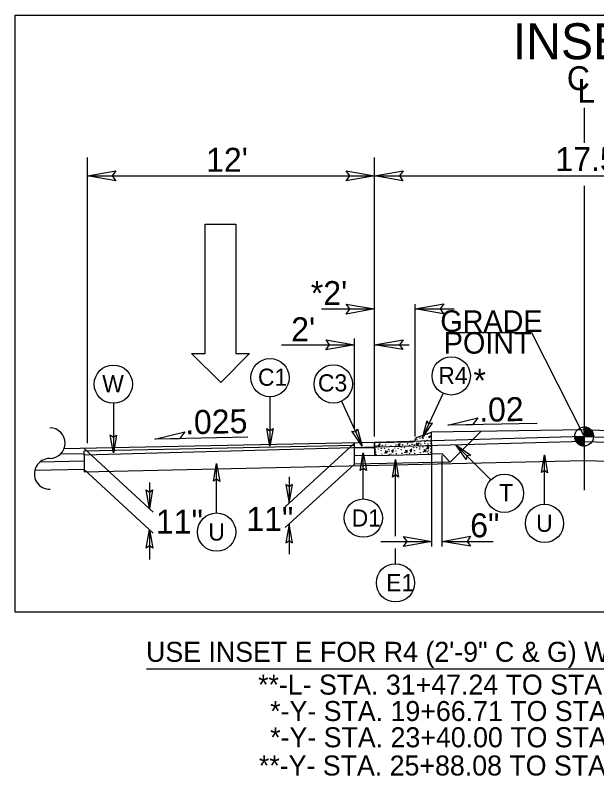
# Model space of a CAD drawing. Extents: x 958711 to 962106, y 831169 to 840840.
# Drawn here: x 959767.6 to 959956.9, y 838795 to 839042.5 of the extents above; entities that cross this region are included whole.
import ezdxf

# ---------------------------------------------------------------- set-up
doc = ezdxf.new("R2010")
doc.units = 0
for name, color, linetype in [('Default', 7, 'Continuous'), ('Old_Level_1', 7, 'Continuous'), ('Old_Level_11', 7, 'Continuous'), ('Old_Level_3', 7, 'Continuous'), ('Prop Dimension Text', 7, 'Continuous'), ('Prop Lane Arrow CELL', 7, 'Continuous'), ('Typical Curb CELL', 7, 'Continuous'), ('Typical ID Circle CELL', 7, 'Continuous'), ('Typical Terminator CELL', 7, 'Continuous'), ('Typical Text Grade Point CELL', 7, 'Continuous'), ('Typical Text ID Circle CELL', 7, 'Continuous')]:
    doc.layers.add(name, color=color, linetype=linetype)

# ---------------------------------------------------------------- blocks, each defined once
blk = doc.blocks.new('Lane Arrow Through')
at = {"layer": 'Prop Lane Arrow CELL'}
for p, q in [((-3.15, 1.6), (-3.15, 3.1)), ((-3.15, 3.1), (0, 0)), ((-17.15, 1.6), (-3.15, 1.6)), ((-17.15, -1.7), (-17.15, 1.6)), ((0, 0), (-3.15, -3.2)), ((-3.15, -1.7), (-17.15, -1.7)), ((-3.15, -3.2), (-3.15, -1.7))]:
    blk.add_line(p, q, dxfattribs=at)

msp = doc.modelspace()

# ---------------------------------------------------------------- linework, layer by layer
at = {"layer": 'Default'}
for p, q in [((959952.78, 839012.37), (959952.78, 839000.98)), ((959952.78, 838987.01), (959952.78, 838887.92)), ((959952.78, 838907.6), (959903.13, 838906.79)), ((959909.22, 838897.09), (959919.17, 838907.05)), ((959952.78, 838907.6), (960002.43, 838906.61))]:
    msp.add_line(p, q, dxfattribs=at)
at = {"layer": 'Old_Level_1'}
for p, q in [((959791.14, 838903.19), (959791.14, 838996.13)), ((959884.62, 838905.42), (959884.62, 838996.13)), ((959791.14, 838990.21), (959884.62, 838990.21)), ((959884.62, 838990.21), (960020.95, 838990.21)), ((959897.84, 838905.42), (959897.84, 838948.48)), ((959867.31, 838946.9), (959884.62, 838946.9)), ((959897.84, 838946.9), (959910.47, 838946.9)), ((959878.02, 838908.11), (959878.02, 838937.33)), ((959854.29, 838935.26), (959878.02, 838935.26)), ((959884.62, 838935.26), (959895.89, 838935.26)), ((959937.48, 838909.64), (959908.42, 838909.05)), ((959952.78, 838905.4), (959952.78, 838908.47)), ((959884.62, 838903.42), (959783.5, 838901.38)), ((959952.78, 838903.76), (959790.06, 838899.33)), ((959843.32, 838905.15), (959813.11, 838904.54)), ((959952.78, 838905.4), (959884.62, 838903.42)), ((959949.72, 838905.4), (959952.78, 838905.4)), ((959955.84, 838905.4), (959952.78, 838905.4)), ((959952.78, 838902.35), (959952.78, 838905.4)), ((959952.78, 838905.4), (959952.78, 838902.35)), ((959952.78, 838905.4), (960020.95, 838903.26)), ((959878.02, 838902.43), (959790.06, 838900.65)), ((959790.06, 838901.51), (959812.57, 838880.8)), ((959878.02, 838903.29), (959855.51, 838882.58)), ((959878.02, 838896.46), (959878.02, 838903.29)), ((959884.66, 838901.7), (959878.02, 838901.56)), ((959790.06, 838899.78), (959782.31, 838899.63)), ((959790.06, 838899.33), (959790.06, 838900.65)), ((959790.06, 838899.33), (959790.06, 838893.87)), ((959884.71, 838899.27), (959878.02, 838899.14)), ((959906.58, 838899.73), (959903.28, 838899.66)), ((959903.28, 838869.65), (959903.28, 838899.66)), ((959906.58, 838899.73), (959909.22, 838897.09)), ((959906.58, 838869.65), (959906.58, 838899.27)), ((959790.06, 838897.36), (959775.63, 838897.06)), ((959878.02, 838896.46), (959855.51, 838875.75)), ((959909.22, 838897.09), (959878.02, 838896.46)), ((959790.06, 838894.68), (959773.99, 838894.36)), ((959790.06, 838894.68), (959812.57, 838873.97)), ((959856.78, 838892.25), (959856.77, 838883.74)), ((959811.3, 838890.47), (959811.31, 838881.96)), ((959856.78, 838876.92), (959856.78, 838867.14)), ((959811.3, 838875.14), (959811.3, 838865.36)), ((959886.68, 838871.29), (959903.28, 838871.29)), ((959906.58, 838871.29), (959923.18, 838871.29)), ((959810.36, 838829.82), (960099.79, 838829.82))]:
    msp.add_line(p, q, dxfattribs=at)
msp.add_lwpolyline([(959767.63, 839042.47), (960126.24, 839042.47), (960126.24, 838848.28), (959767.63, 838848.28)], close=True, dxfattribs=at)
for points in [[(959952.82, 838908.47), (959952.82, 838908.47), (959952.82, 838905.4)], [(959952.87, 838908.47), (959952.87, 838905.4)], [(959952.94, 838908.46), (959952.94, 838905.4)], [(959953, 838908.45), (959953, 838905.4)], [(959953.06, 838908.45), (959953.06, 838905.4)], [(959953.12, 838908.45), (959953.12, 838905.4)], [(959953.19, 838908.44), (959953.19, 838905.4)], [(959953.25, 838908.44), (959953.25, 838905.4)], [(959953.3, 838908.41), (959953.3, 838905.4)], [(959953.36, 838908.41), (959953.36, 838905.4)], [(959953.43, 838908.4), (959953.43, 838905.4)], [(959953.49, 838908.38), (959953.49, 838905.4)], [(959953.55, 838908.36), (959953.55, 838905.4)], [(959953.61, 838908.34), (959953.61, 838905.4)], [(959953.68, 838908.33), (959953.68, 838905.4)], [(959953.73, 838908.31), (959953.73, 838905.4)], [(959953.8, 838908.29), (959953.79, 838905.4)], [(959953.85, 838908.27), (959953.85, 838905.4)], [(959953.91, 838908.25), (959953.91, 838905.4)], [(959953.98, 838908.22), (959953.98, 838905.4)], [(959954.04, 838908.2), (959954.04, 838905.4)], [(959954.1, 838908.16), (959954.1, 838905.4)], [(959954.16, 838908.14), (959954.16, 838905.4)], [(959954.22, 838908.12), (959954.22, 838905.4)], [(959954.28, 838908.08), (959954.28, 838905.4)], [(959954.35, 838908.04), (959954.35, 838905.4)], [(959954.41, 838908), (959954.41, 838905.4)], [(959954.47, 838907.96), (959954.47, 838905.4)], [(959954.53, 838907.91), (959954.53, 838905.4)], [(959954.58, 838907.88), (959954.58, 838905.4)], [(959954.65, 838907.83), (959954.65, 838905.4)], [(959954.71, 838907.78), (959954.71, 838905.4)], [(959954.77, 838907.74), (959954.77, 838905.4)], [(959954.83, 838907.68), (959954.83, 838905.4)], [(959954.89, 838907.62), (959954.89, 838905.4)], [(959954.96, 838907.55), (959954.96, 838905.4)], [(959955.02, 838907.49), (959955.02, 838905.4)], [(959955.08, 838907.43), (959955.08, 838905.4)], [(959955.14, 838907.37), (959955.14, 838905.4)], [(959955.2, 838907.27), (959955.2, 838905.4)], [(959955.27, 838907.2), (959955.27, 838905.4)], [(959955.33, 838907.11), (959955.33, 838905.4)], [(959955.39, 838907.02), (959955.39, 838905.4)], [(959955.44, 838906.92), (959955.44, 838905.4)], [(959955.5, 838906.81), (959955.5, 838905.4)], [(959955.56, 838906.67), (959955.56, 838905.4)], [(959955.63, 838906.52), (959955.63, 838905.4)], [(959955.69, 838906.36), (959955.69, 838905.4)], [(959955.75, 838906.15), (959955.75, 838905.4)], [(959955.81, 838905.85), (959955.81, 838905.4)], [(959949.75, 838905.4), (959949.75, 838905.08)], [(959949.81, 838905.4), (959949.81, 838904.71)], [(959949.87, 838905.4), (959949.87, 838904.49)], [(959949.93, 838905.4), (959949.93, 838904.31)], [(959950, 838905.4), (959950, 838904.17)], [(959950.06, 838905.4), (959950.06, 838904.04)], [(959950.11, 838905.4), (959950.11, 838903.92)], [(959950.17, 838905.4), (959950.17, 838903.81)], [(959950.24, 838905.4), (959950.24, 838903.73)], [(959950.3, 838905.4), (959950.3, 838903.64)], [(959950.36, 838905.4), (959950.36, 838903.54)], [(959950.42, 838905.4), (959950.42, 838903.48)], [(959950.48, 838905.4), (959950.48, 838903.41)], [(959950.54, 838905.4), (959950.54, 838903.33)], [(959950.6, 838905.4), (959950.6, 838903.26)], [(959950.66, 838905.4), (959950.66, 838903.21)], [(959950.73, 838905.4), (959950.73, 838903.16)], [(959950.79, 838905.4), (959950.79, 838903.1)], [(959950.85, 838905.4), (959950.85, 838903.05)], [(959950.91, 838905.4), (959950.91, 838902.99)], [(959950.97, 838905.4), (959950.97, 838902.95)], [(959951.03, 838905.4), (959951.03, 838902.91)], [(959951.09, 838905.4), (959951.09, 838902.87)], [(959951.15, 838905.4), (959951.15, 838902.82)], [(959951.22, 838905.4), (959951.22, 838902.78)], [(959951.28, 838905.4), (959951.28, 838902.74)], [(959951.34, 838905.4), (959951.34, 838902.71)], [(959951.39, 838905.4), (959951.39, 838902.69)], [(959951.45, 838905.4), (959951.45, 838902.66)], [(959951.52, 838905.4), (959951.52, 838902.62)], [(959951.58, 838905.4), (959951.58, 838902.6)], [(959951.64, 838905.4), (959951.64, 838902.57)], [(959951.7, 838905.4), (959951.7, 838902.55)], [(959951.77, 838905.4), (959951.77, 838902.53)], [(959951.82, 838905.4), (959951.82, 838902.5)], [(959951.89, 838905.4), (959951.89, 838902.49)], [(959951.95, 838905.4), (959951.95, 838902.47)], [(959952.01, 838905.4), (959952.01, 838902.45)], [(959952.07, 838905.4), (959952.07, 838902.44)], [(959952.13, 838905.4), (959952.13, 838902.42)], [(959952.2, 838905.4), (959952.2, 838902.41)], [(959952.25, 838905.4), (959952.25, 838902.41)], [(959952.31, 838905.4), (959952.31, 838902.39)], [(959952.37, 838905.4), (959952.37, 838902.37)], [(959952.44, 838905.4), (959952.44, 838902.37)], [(959952.5, 838905.4), (959952.5, 838902.37)], [(959952.56, 838905.4), (959952.56, 838902.35)], [(959952.62, 838905.4), (959952.62, 838902.35)], [(959952.68, 838905.4), (959952.68, 838902.35)], [(959952.74, 838905.4), (959952.74, 838902.35), (959952.74, 838902.35)], [(959952.78, 838903.76), (960111.06, 838899.45)], [(959790.06, 838893.87), (959952.94, 838897.58)], [(959952.94, 838897.58), (960111.06, 838893.27)]]:
    msp.add_lwpolyline(points, dxfattribs=at)
msp.add_circle((959952.79, 838905.41), 3.06, dxfattribs=at)
for centre, radius, start, end in [((959952.79, 838905.41), 3.06, 359.9905, 89.9905), ((959778.86, 838903.25), 5, 270, 90), ((959952.79, 838905.41), 3.06, 179.9905, 269.9905), ((959778.86, 838893.25), 5, 90, 272.2728)]:
    msp.add_arc(centre, radius, start, end, dxfattribs=at)
at = {"layer": 'Old_Level_11'}
for p, q in [((959908.42, 838909.05), (959918.17, 838911.48)), ((959918.17, 838911.48), (959916.44, 838909.21)), ((959916.44, 838909.21), (959908.42, 838909.05)), ((959813.11, 838904.54), (959822.87, 838906.97)), ((959822.87, 838906.97), (959821.13, 838904.7)), ((959821.13, 838904.7), (959813.11, 838904.54))]:
    msp.add_line(p, q, dxfattribs=at)
at = {"layer": 'Typical Curb CELL'}
for p, q in [((959898.29, 838905.05), (959903.13, 838906.78)), ((959903.28, 838899.66), (959903.13, 838906.78)), ((959884.62, 838903.42), (959897.19, 838903.69)), ((959884.62, 838903.42), (959884.71, 838899.27)), ((959884.71, 838899.27), (959884.62, 838903.38)), ((959897.84, 838904.37), (959897.84, 838904.41)), ((959898.29, 838902.94), (959898.87, 838903.37)), ((959898.87, 838903.37), (959898.59, 838902.3)), ((959902.35, 838905.57), (959902.96, 838905.59)), ((959902.4, 838904.96), (959902.35, 838905.57)), ((959902.96, 838905.59), (959902.4, 838904.96)), ((959885.73, 838902.51), (959886.31, 838902.93)), ((959886.03, 838901.87), (959885.73, 838902.51)), ((959886.31, 838902.93), (959886.03, 838901.87)), ((959890.7, 838901.08), (959890.07, 838900.72)), ((959890.5, 838900.15), (959890.7, 838901.08)), ((959892.27, 838902.76), (959892.85, 838903.18)), ((959892.58, 838902.11), (959892.27, 838902.76)), ((959892.85, 838903.18), (959892.58, 838902.11)), ((959894.73, 838900.98), (959895.24, 838900.89)), ((959895, 838900.11), (959894.73, 838900.98)), ((959895.24, 838900.89), (959895, 838900.11)), ((959896.72, 838901.26), (959896.09, 838900.9)), ((959896.09, 838900.9), (959896.51, 838900.33)), ((959896.51, 838900.33), (959896.72, 838901.26)), ((959898.59, 838902.3), (959898.29, 838902.94)), ((959900.74, 838901.16), (959901.26, 838901.07)), ((959901.02, 838900.29), (959900.74, 838901.16)), ((959901.26, 838901.07), (959901.02, 838900.29)), ((959901.74, 838902.21), (959902.26, 838902.12)), ((959902.01, 838901.34), (959901.74, 838902.21)), ((959902.26, 838902.12), (959902.01, 838901.34)), ((959884.71, 838899.27), (959903.28, 838899.66)), ((959888.19, 838900.72), (959888.7, 838900.64)), ((959888.46, 838899.86), (959888.19, 838900.72)), ((959888.7, 838900.64), (959888.46, 838899.86)), ((959890.07, 838900.72), (959890.5, 838900.15))]:
    msp.add_line(p, q, dxfattribs=at)
for centre in [(959901.89, 838906.17), (959886.23, 838903.32), (959898.33, 838904.47), (959899.4, 838904.93), (959899.56, 838903.78), (959900.37, 838904.79), (959900.74, 838905.57), (959900.91, 838903.77), (959901.38, 838905.2), (959901.74, 838904.15), (959902.9, 838903.88), (959884.73, 838901.36), (959885.06, 838902.36), (959885.76, 838901.35), (959886.73, 838900.92), (959886.81, 838901.59), (959887.12, 838902.53), (959887.78, 838901.52), (959888.18, 838902.65), (959889.01, 838902.7), (959889.12, 838902.91), (959889.2, 838901.26), (959889.93, 838902.38), (959891.27, 838901.61), (959891.6, 838902.61), (959892.3, 838901.6), (959893.27, 838901.17), (959893.36, 838901.84), (959893.66, 838902.78), (959894.32, 838901.77), (959895.32, 838903.01), (959895.64, 838901.62), (959895.95, 838902.56), (959896.78, 838902.83), (959897.29, 838901.79), (959897.62, 838902.79), (959898.22, 838903.3), (959898.32, 838901.78), (959899.09, 838903.12), (959899.29, 838901.35), (959899.37, 838902.03), (959899.67, 838902.97), (959900.34, 838901.95), (959900.99, 838903.22), (959901.53, 838901.49), (959901.97, 838902.97), (959902.74, 838901.29), (959902.85, 838903.11), (959902.89, 838902.22), (959884.97, 838900.4), (959885.09, 838899.53), (959886.95, 838899.7), (959887.97, 838900.01), (959889.33, 838900.7), (959889.35, 838899.6), (959889.89, 838899.71), (959891.51, 838900.65), (959891.63, 838899.78), (959893.49, 838899.95), (959894.51, 838900.26), (959895.91, 838899.89), (959897.53, 838900.83), (959897.65, 838899.96), (959899.51, 838900.13), (959900.53, 838900.44), (959901.8, 838900.43), (959902.16, 838899.96), (959902.78, 838900.13), (959903.03, 838900.62)]:
    msp.add_circle(centre, 0.0452, dxfattribs=at)
for centre, radius, start, end in [((959897.18, 838904.35), 0.667, 271.206, 1.206), ((959898.51, 838904.42), 0.667, 109.641, 181.206), ((959895.14, 838899.53), 0.0452, 26.9645, 154.1675), ((959901.16, 838899.72), 0.0452, 26.9645, 154.1675), ((959902.15, 838900.77), 0.0452, 26.9645, 154.1675)]:
    msp.add_arc(centre, radius, start, end, dxfattribs=at)
at = {"layer": 'Typical ID Circle CELL'}
for p, q in [((959850.55, 838918.33), (959850.55, 838902.24)), ((959906.9, 838919.48), (959900.1, 838904.9)), ((959799.57, 838916.21), (959799.57, 838900.12)), ((959873.78, 838916.87), (959880.58, 838902.29)), ((959922.45, 838891.34), (959911.07, 838902.71)), ((959880.93, 838885.08), (959880.93, 838900.09)), ((959939.9, 838883.35), (959939.9, 838899.44)), ((959833.18, 838880.53), (959833.18, 838896.61)), ((959891.41, 838872.94), (959891.41, 838897.97)), ((959891.41, 838864.03), (959891.41, 838869.01))]:
    msp.add_line(p, q, dxfattribs=at)
for centre in [(959850.55, 838924.55), (959909.53, 838925.13), (959799.57, 838922.43), (959871.15, 838922.51), (959926.85, 838886.94), (959880.93, 838878.85), (959939.9, 838877.13), (959833.18, 838874.3), (959891.41, 838857.8)]:
    msp.add_circle(centre, 6.23, dxfattribs=at)
at = {"layer": 'Typical Terminator CELL'}
for points in [[(959800.36, 838988.62), (959791.14, 838990.21), (959800.41, 838991.85), (959799.24, 838990.21)], [(959875.4, 838991.79), (959884.62, 838990.21), (959875.35, 838988.57), (959876.53, 838990.21)], [(959893.84, 838988.62), (959884.62, 838990.21), (959893.89, 838991.85), (959892.72, 838990.21)], [(959875.4, 838948.49), (959884.62, 838946.9), (959875.35, 838945.26), (959876.53, 838946.9)], [(959907.06, 838945.31), (959897.84, 838946.9), (959907.12, 838948.54), (959905.94, 838946.9)], [(959868.79, 838936.85), (959878.02, 838935.26), (959868.74, 838933.62), (959869.92, 838935.26)], [(959893.84, 838933.67), (959884.62, 838935.26), (959893.89, 838936.9), (959892.72, 838935.26)], [(959901.64, 838910.55), (959900.1, 838904.9), (959903.48, 838909.72), (959902.24, 838909.49)], [(959800.56, 838905.89), (959799.57, 838900.12), (959798.54, 838905.92), (959799.57, 838905.18)], [(959851.55, 838908.01), (959850.55, 838902.24), (959849.53, 838908.04), (959850.55, 838907.3)], [(959879.04, 838907.93), (959880.58, 838902.29), (959877.2, 838907.11), (959878.44, 838906.88)], [(959914.44, 838897.94), (959911.07, 838902.71), (959915.89, 838899.34), (959914.65, 838899.14)], [(959879.94, 838894.33), (959880.93, 838900.09), (959881.96, 838894.3), (959880.93, 838895.03)], [(959938.9, 838893.67), (959939.9, 838899.44), (959940.92, 838893.64), (959939.9, 838894.38)], [(959832.19, 838890.85), (959833.18, 838896.61), (959834.21, 838890.82), (959833.18, 838891.55)], [(959890.41, 838892.2), (959891.41, 838897.97), (959892.43, 838892.17), (959891.41, 838892.91)], [(959855.73, 838889.81), (959856.77, 838883.74), (959857.85, 838889.84), (959856.78, 838889.06)], [(959812.35, 838888.03), (959811.31, 838881.96), (959810.23, 838888.06), (959811.3, 838887.28)], [(959857.83, 838870.86), (959856.78, 838876.92), (959855.7, 838870.82), (959856.78, 838871.6)], [(959810.25, 838869.08), (959811.3, 838875.14), (959812.38, 838869.04), (959811.3, 838869.82)], [(959894.06, 838872.87), (959903.28, 838871.29), (959894.01, 838869.65), (959895.19, 838871.29)], [(959915.81, 838869.7), (959906.58, 838871.29), (959915.86, 838872.93), (959914.68, 838871.29)]]:
    msp.add_lwpolyline(points, close=True, dxfattribs=at)
at = {"layer": 'Typical Text Grade Point CELL'}
for p, q in [((959910.35, 838939.19), (959935.67, 838939.19)), ((959935.67, 838939.19), (959952.78, 838905.4))]:
    msp.add_line(p, q, dxfattribs=at)

# ---------------------------------------------------------------- block references
at = {"layer": 'Old_Level_1', "xscale": 3, "yscale": 3, "rotation": -90.00000000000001}
msp.add_blockref('Lane Arrow Through', (959834.59, 838922.99), dxfattribs=at)

# ---------------------------------------------------------------- texts
at = {"layer": 'Old_Level_1'}
for s, height, p in [('INSET E', 11.716, (959929.59, 839028.13)), ('USE INSET E FOR R4 (2\'-9" C & G) WITH TYPICAL SECTION NO. 4', 6.5088, (959810.22, 838832.1))]:
    msp.add_text(s, height=height, dxfattribs=at).set_placement(p)
at = {"layer": 'Old_Level_11'}
for s, p in [('GRADE', (959905.99, 838939.44)), ('POINT', (959907.12, 838932.37))]:
    msp.add_text(s, height=7, dxfattribs=at).set_placement(p)
at = {"layer": 'Old_Level_3'}
for s, p in [('**-L- STA. 31+47.24 TO STA. 37+61.00 RT. MEDIAN', (959846.68, 838821.43)), ('*-Y- STA. 19+66.71 TO STA. 20+51.00 LT. MEDIAN', (959850.62, 838812.84)), ('*-Y- STA. 23+40.00 TO STA. 25+88.08 LT. MEDIAN', (959850.62, 838804.3)), ('**-Y- STA. 25+88.08 TO STA. 32+03.51 RT. MEDIAN', (959846.95, 838795.12))]:
    msp.add_text(s, height=6.5088, dxfattribs=at).set_placement(p)
at = {"layer": 'Prop Dimension Text'}
for s, height, rotation, p in [('C', 7.77, 0, (959947.17, 839018.08)), ('L', 7.77, 0, (959950.57, 839013.98)), ("12'", 7.801, 0, (959829.75, 838991.52)), ("17.5'", 7.801, 0, (959943.44, 838991.74)), ("*2'", 7.801, 0, (959863.84, 838948.16)), ("2'", 7.801, 0, (959857.45, 838936.39)), ('*', 7.8, 0, (959916.77, 838919.72)), ('.02', 7.801, 1.1839, (959918.69, 838910.16)), ('.025', 7.801, 1.1839, (959822.98, 838906.12)), ('11"', 7.801, 0, (959813.42, 838873.81)), ('11"', 7.801, 0, (959842.84, 838874.64)), ('6"', 7.801, 0, (959915.71, 838872.61))]:
    msp.add_text(s, height=height, rotation=rotation, dxfattribs=at).set_placement(p)
at = {"layer": 'Typical Text ID Circle CELL'}
for s, height, p in [('C1', 5.572, (959846.64, 838921.92)), ('C3', 5.572, (959866.17, 838920.07)), ('R4', 5.572, (959905.33, 838922.5)), ('W', 5.57, (959795.95, 838919.8)), ('T', 5.57, (959925.16, 838884.37)), ('D1', 5.572, (959877.14, 838876.11)), ('U', 5.57, (959937.19, 838874.39)), ('U', 5.57, (959830.48, 838871.56)), ('E1', 5.572, (959888.37, 838855.06))]:
    msp.add_text(s, height=height, dxfattribs=at).set_placement(p)

doc.saveas('drawing.dxf')
